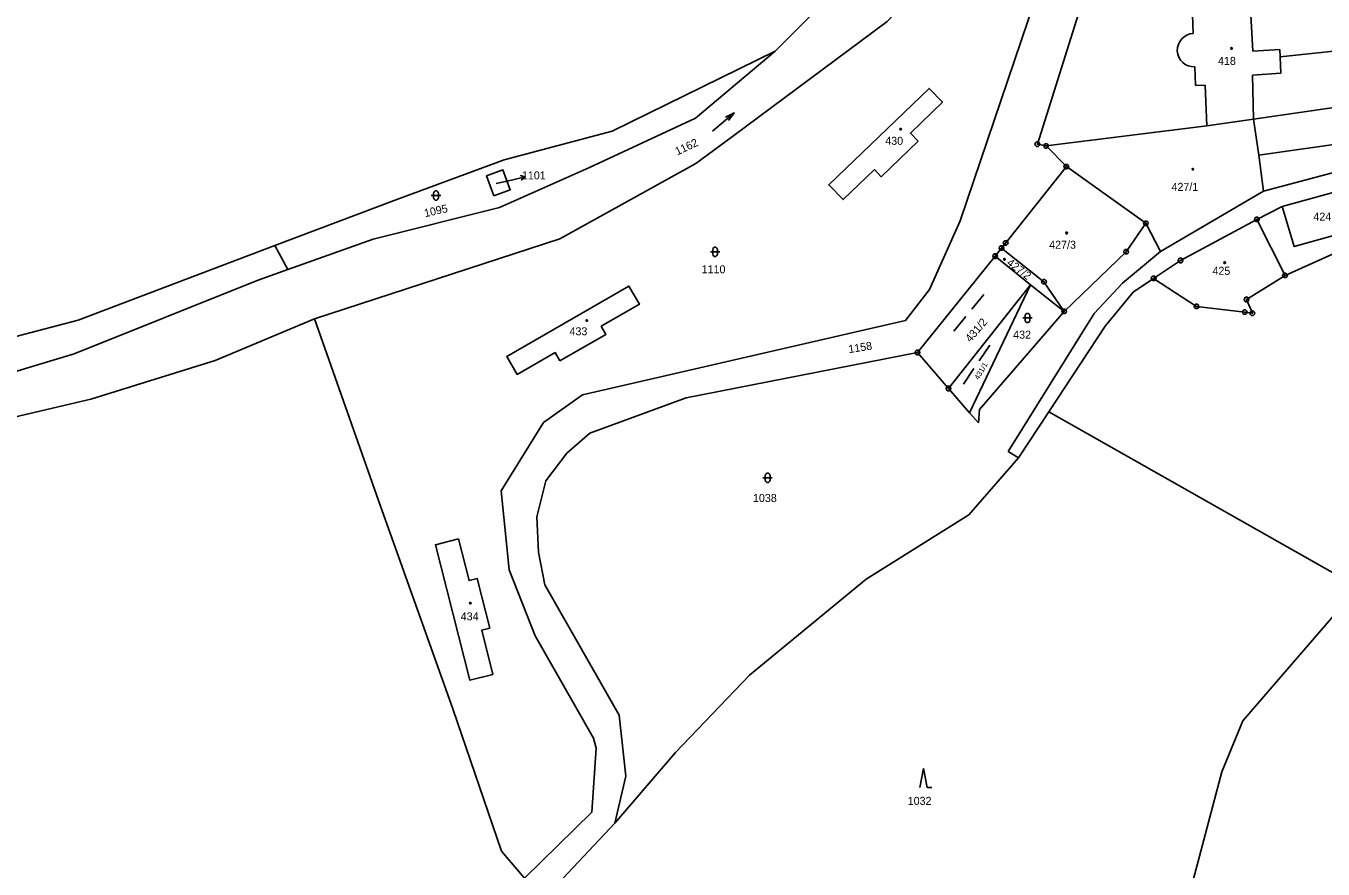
# Model space of a CAD drawing. Extents: x -812394 to -807601, y -1013098 to -1009266.
# Drawn here: x -811273.1 to -810997.6, y -1011891.6 to -1011712.3 of the extents above; entities that cross this region are included whole.
import ezdxf

# ---------------------------------------------------------------- set-up
doc = ezdxf.new("R2010")
doc.units = 0
for name, color, linetype in [('KN_HRANICE', 7, 'Continuous'), ('KN_KULTURY', 7, 'Continuous'), ('KN_MEZNIKY', 7, 'Continuous'), ('KN_PARCELY', 7, 'Continuous'), ('KN_SLUCKY', 7, 'Continuous')]:
    doc.layers.add(name, color=color, linetype=linetype)

# ---------------------------------------------------------------- blocks, each defined once
blk = doc.blocks.new('308')
blk.add_lwpolyline([(-0.75, 0), (0, 4), (0.75, 0), (1.75, 0)])
blk = doc.blocks.new('316')
for points in [[(-1, 1), (0.27, 1), (1, 1)], [(-0.5, 1.5), (-0.4, 1.79), (-0.15, 1.97), (0.16, 1.97), (0.41, 1.79), (0.51, 1.5), (0.51, 0.5), (0.41, 0.21), (0.16, 0.03), (-0.15, 0.03), (-0.4, 0.21), (-0.5, 0.5), (-0.5, 1.5)]]:
    blk.add_lwpolyline(points)
blk = doc.blocks.new('NAHRADNI_SYMBOL')
blk.add_lwpolyline([(0.09, 0.15), (0.18, 0), (0.09, -0.15), (-0.09, -0.15), (-0.18, 0), (-0.09, 0.15), (0.09, 0.15)])
blk = doc.blocks.new('802')
blk.add_line((-3, 0), (3, 0))
blk.add_lwpolyline([(1, 0.5), (3, 0), (1, -0.5)])
blk = doc.blocks.new('803')
for p, q in [((-7.5, 0), (-1.5, 0)), ((1.5, 0), (7.5, 0))]:
    blk.add_line(p, q)
blk = doc.blocks.new('10292')
blk.add_line((0, 3), (0, 0))
blk.add_lwpolyline([(-0.5, 2), (0, 3), (0.5, 2)])
blk = doc.blocks.new('105')
blk.add_line((-0.12, 0), (0.12, 0))
blk.add_lwpolyline([(0.15, 0.48), (0.4, 0.3), (0.5, 0.01), (0.4, -0.28), (0.15, -0.46), (-0.16, -0.46), (-0.41, -0.28), (-0.51, 0.01), (-0.41, 0.3), (-0.16, 0.48), (0.15, 0.48)])
blk = doc.blocks.new('402')
blk.add_lwpolyline([(0.09, 0.15), (0.18, 0), (0.09, -0.15), (-0.09, -0.15), (-0.18, 0), (-0.09, 0.15), (0.09, 0.15)])

msp = doc.modelspace()

# ---------------------------------------------------------------- linework, layer by layer
at = {"layer": 'KN_HRANICE'}
for p, q in [((-811036.27, -1011667.85), (-811058.25, -1011737.49)), ((-811113.97, -1011717.72), (-811101.04, -1011704.72)), ((-811025.3, -1011710.01), (-811025.13, -1011713.95)), ((-811148.58, -1011734.71), (-811113.97, -1011717.72)), ((-811024.65, -1011724.99), (-811024.82, -1011721.05)), ((-811022.63, -1011724.91), (-811024.65, -1011724.99)), ((-811022.25, -1011733.58), (-811022.63, -1011724.91)), ((-811022.25, -1011733.58), (-811012.33, -1011732.15)), ((-811012.33, -1011732.15), (-811011.17, -1011739.82)), ((-811171.54, -1011740.78), (-811148.58, -1011734.71)), ((-811056.39, -1011737.86), (-811022.25, -1011733.58)), ((-811058.25, -1011737.49), (-811056.39, -1011737.86)), ((-811056.39, -1011737.86), (-811052.09, -1011742.26)), ((-811011.17, -1011739.82), (-811010.19, -1011747.48)), ((-811010.19, -1011747.48), (-810977.33, -1011738.74)), ((-811194.29, -1011749.24), (-811171.54, -1011740.78)), ((-811052.09, -1011742.26), (-811064.98, -1011758.48)), ((-811035.21, -1011754.31), (-811052.09, -1011742.26)), ((-811012.74, -1011748.94), (-811010.19, -1011747.48)), ((-810990.56, -1011746.41), (-811006.21, -1011750.72)), ((-811220.22, -1011759.06), (-811194.29, -1011749.24)), ((-811199.35, -1011757.68), (-811172.54, -1011750.96)), ((-811032.06, -1011760.31), (-811012.74, -1011748.94)), ((-811006.21, -1011750.72), (-811011.62, -1011753.48)), ((-811074.63, -1011753.78), (-811081.18, -1011768.41)), ((-811039.37, -1011760.37), (-811035.21, -1011754.31)), ((-811035.21, -1011754.31), (-811032.06, -1011760.31)), ((-811011.62, -1011753.48), (-811005.63, -1011765.4)), ((-811262.02, -1011774.9), (-811220.22, -1011759.06)), ((-811217.49, -1011764.12), (-811220.22, -1011759.06)), ((-811217.49, -1011764.12), (-811199.35, -1011757.68)), ((-811065.85, -1011759.58), (-811067.22, -1011761.3)), ((-811064.98, -1011758.48), (-811065.85, -1011759.58)), ((-811056.84, -1011766.74), (-811065.85, -1011759.58)), ((-811005.63, -1011765.4), (-810987.54, -1011757.25)), ((-811067.22, -1011761.3), (-811083.69, -1011781.79)), ((-811067.22, -1011761.3), (-811059.74, -1011767.4)), ((-811052.53, -1011773.05), (-811039.37, -1011760.37)), ((-811032.06, -1011760.31), (-811040.13, -1011767.06)), ((-811224.02, -1011766.44), (-811217.49, -1011764.12)), ((-811262.9, -1011782.04), (-811224.02, -1011766.44)), ((-811077.11, -1011789.44), (-811059.74, -1011767.4)), ((-811059.74, -1011767.4), (-811072.69, -1011794.59)), ((-811059.74, -1011767.4), (-811052.53, -1011773.05)), ((-811052.53, -1011773.05), (-811056.84, -1011766.74)), ((-811040.13, -1011767.06), (-811046.19, -1011773.46)), ((-811037.93, -1011768.93), (-811033.54, -1011766.01)), ((-811081.18, -1011768.41), (-811086.29, -1011774.95)), ((-811043.81, -1011776.2), (-811037.93, -1011768.93)), ((-811070.51, -1011793.88), (-811052.53, -1011773.05)), ((-811046.19, -1011773.46), (-811064.47, -1011802.81)), ((-811014.19, -1011773.19), (-811012.57, -1011773.41)), ((-811296.53, -1011783.87), (-811262.02, -1011774.9)), ((-811154.9, -1011790.75), (-811088.72, -1011775.51)), ((-811086.29, -1011774.95), (-811088.72, -1011775.51)), ((-811055.79, -1011794.38), (-811043.81, -1011776.2)), ((-811132.85, -1011791.42), (-811083.69, -1011781.79)), ((-811083.69, -1011781.79), (-811077.11, -1011789.44)), ((-811291.86, -1011790.78), (-811262.9, -1011782.04)), ((-811077.11, -1011789.44), (-811072.69, -1011794.59)), ((-811153.33, -1011798.9), (-811132.85, -1011791.42)), ((-811072.69, -1011794.59), (-811070.75, -1011796.69)), ((-811070.75, -1011796.69), (-811070.51, -1011793.88)), ((-811055.79, -1011794.38), (-811062.22, -1011804.13)), ((-810990.1, -1011831.63), (-811055.79, -1011794.38)), ((-811158.17, -1011803.18), (-811153.33, -1011798.9)), ((-811162.67, -1011809.02), (-811158.17, -1011803.18)), ((-811064.47, -1011802.81), (-811062.22, -1011804.13)), ((-811062.22, -1011804.13), (-811072.81, -1011816.28)), ((-811164.61, -1011816.73), (-811162.67, -1011809.02)), ((-811164.22, -1011824.22), (-811164.61, -1011816.73)), ((-811072.81, -1011816.28), (-811094.61, -1011829.98)), ((-811162.9, -1011831.15), (-811164.22, -1011824.22)), ((-811147.06, -1011858.89), (-811162.9, -1011831.15)), ((-811094.61, -1011829.98), (-811119.39, -1011850.37)), ((-811014.6, -1011860.1), (-810990.1, -1011831.63)), ((-811152.56, -1011863.74), (-811164.95, -1011842)), ((-811119.39, -1011850.37), (-811135.1, -1011866.8)), ((-811145.65, -1011871.81), (-811147.06, -1011858.89)), ((-811019.07, -1011870.93), (-811014.6, -1011860.1)), ((-811152.56, -1011863.74), (-811151.94, -1011865.87)), ((-811151.94, -1011865.87), (-811152.86, -1011879.52)), ((-811135.1, -1011866.8), (-811148, -1011881.85)), ((-811148, -1011881.85), (-811145.65, -1011871.81)), ((-811025.42, -1011895.01), (-811019.07, -1011870.93)), ((-811152.86, -1011879.52), (-811167.19, -1011893.49)), ((-811162.39, -1011897.16), (-811148, -1011881.85)), ((-811167.19, -1011893.49), (-811172.1, -1011887.81))]:
    msp.add_line(p, q, dxfattribs=at)
for points in [[(-811123.04, -1011735.83), (-811090.17, -1011711.42), (-811052.04, -1011671.11)], [(-811074.63, -1011753.78), (-811047.22, -1011672.77), (-811052.04, -1011671.11)], [(-811172.54, -1011750.96), (-811153.38, -1011742.41), (-811130.88, -1011731.98), (-811113.97, -1011717.72)], [(-811211.84, -1011774.62), (-811159.7, -1011757.62), (-811130.79, -1011741.59), (-811123.04, -1011735.83)], [(-811011.62, -1011753.48), (-811027.82, -1011762.22), (-811033.54, -1011766.01)], [(-811033.54, -1011766.01), (-811024.43, -1011771.98), (-811014.19, -1011773.19)], [(-811012.57, -1011773.41), (-811013.82, -1011770.52), (-811005.63, -1011765.4)], [(-811440.11, -1011849.96), (-811421.34, -1011843.71), (-811392.71, -1011835.04), (-811348.09, -1011817.52), (-811325.66, -1011813.58), (-811310.88, -1011808.15), (-811285.31, -1011797.78), (-811259.35, -1011791.72), (-811232.94, -1011783.44), (-811211.84, -1011774.62)], [(-811211.84, -1011774.62), (-811198.18, -1011813.24), (-811182.45, -1011857.53), (-811172.1, -1011887.81)], [(-811164.95, -1011842), (-811170.42, -1011827.98), (-811172.16, -1011811.18), (-811163.19, -1011796.67), (-811154.9, -1011790.75)]]:
    msp.add_lwpolyline(points, dxfattribs=at)
for points in [[(-811083.54, -1011736.84), (-811085.2, -1011735.12), (-811078.41, -1011728.58), (-811081.26, -1011725.62), (-811102.55, -1011746.13), (-811099.51, -1011749.28), (-811092.87, -1011742.88), (-811091.4, -1011744.41)], [(-811173.73, -1011748.46), (-811175.25, -1011744.2), (-811171.79, -1011742.97), (-811170.25, -1011747.2)], [(-811159.68, -1011783.56), (-811149.9, -1011777.92), (-811150.9, -1011776.18), (-811142.78, -1011771.5), (-811145, -1011767.65), (-811170.97, -1011782.61), (-811168.77, -1011786.43), (-811160.71, -1011781.78)], [(-811174.55, -1011840.37), (-811177.23, -1011829.82), (-811178.98, -1011830.26), (-811181.24, -1011821.4), (-811186.11, -1011822.64), (-811178.79, -1011851.46), (-811173.9, -1011850.21), (-811176.29, -1011840.82)]]:
    msp.add_lwpolyline(points, close=True, dxfattribs=at)
msp.add_arc((-811024.97, -1011717.5), 3.55, 92.5841, 272.416, dxfattribs=at)
at = {"layer": 'KN_PARCELY'}
msp.add_line((-811173.23, -1011745.87), (-811169.97, -1011745.11), dxfattribs=at)
at = {"layer": 'KN_SLUCKY'}
for p, q in [((-811013.26, -1011702.91), (-811012.49, -1011717.69)), ((-810956.56, -1011713.43), (-811006.65, -1011718.94)), ((-811012.49, -1011717.69), (-811006.72, -1011717.38)), ((-811006.72, -1011717.38), (-811006.65, -1011718.94)), ((-811006.65, -1011718.94), (-811006.5, -1011722.41)), ((-811006.5, -1011722.41), (-811012.56, -1011722.82)), ((-811012.56, -1011722.82), (-811012.33, -1011732.15)), ((-811012.33, -1011732.15), (-810979.82, -1011727.46)), ((-810978.44, -1011735.16), (-811011.17, -1011739.82))]:
    msp.add_line(p, q, dxfattribs=at)
msp.add_lwpolyline([(-811006.21, -1011750.72), (-811003.67, -1011759.26), (-810988.18, -1011754.95)], dxfattribs=at)

# ---------------------------------------------------------------- block references
at = {"layer": 'KN_KULTURY'}
for name, p in [('402', (-811017, -1011717.11)), ('NAHRADNI_SYMBOL', (-811087.3, -1011734.32)), ('NAHRADNI_SYMBOL', (-811025.21, -1011742.82)), ('316', (-811186, -1011749.4)), ('NAHRADNI_SYMBOL', (-811052.04, -1011756.37)), ('316', (-811126.72, -1011761.38)), ('NAHRADNI_SYMBOL', (-811065.24, -1011761.97)), ('NAHRADNI_SYMBOL', (-811018.46, -1011762.68)), ('316', (-811060.35, -1011775.43)), ('NAHRADNI_SYMBOL', (-811153.97, -1011774.97)), ('316', (-811115.55, -1011809.42)), ('NAHRADNI_SYMBOL', (-811178.7, -1011835.04)), ('308', (-811082.43, -1011874.22))]:
    msp.add_blockref(name, p, dxfattribs=at)
at = {"layer": 'KN_KULTURY', "rotation": 40.221637}
msp.add_blockref('802', (-811124.97, -1011732.75), dxfattribs=at)
at = {"layer": 'KN_KULTURY', "xscale": 0.67}
for p, yscale, rotation in [((-811072.82, -1011773.33), 0.6699999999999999, 50.706765), ((-811071.16, -1011784.36), 0.67, 56.092568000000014)]:
    msp.add_blockref('803', p, dxfattribs=dict(at, yscale=yscale, rotation=rotation))
at = {"layer": 'KN_MEZNIKY'}
for p in [(-811058.25, -1011737.49), (-811056.39, -1011737.86), (-811052.09, -1011742.26), (-811035.21, -1011754.31), (-811011.62, -1011753.48), (-811065.85, -1011759.58), (-811064.98, -1011758.48), (-811067.22, -1011761.3), (-811039.37, -1011760.37), (-811027.82, -1011762.22), (-811005.63, -1011765.4), (-811056.84, -1011766.74), (-811033.54, -1011766.01), (-811013.82, -1011770.52), (-811052.53, -1011773.05), (-811024.43, -1011771.98), (-811014.19, -1011773.19), (-811012.57, -1011773.41), (-811083.69, -1011781.79), (-811077.11, -1011789.44)]:
    msp.add_blockref('105', p, dxfattribs=at)
at = {"layer": 'KN_PARCELY', "rotation": -76.95884900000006}
msp.add_blockref('10292', (-811169.97, -1011745.11), dxfattribs=at)

# ---------------------------------------------------------------- texts
at = {"layer": 'KN_PARCELY'}
for s, height, p in [('418', 1.7, (-811019.87, -1011720.63)), ('430', 1.7, (-811090.56, -1011737.62)), ('1101', 1.7, (-811167.75, -1011744.97)), ('1101', 0.1, (-811172.93, -1011745.76)), ('427/1', 1.7, (-811029.75, -1011747.41)), ('424', 1.7, (-810999.61, -1011753.73)), ('427/3', 1.7, (-811055.74, -1011759.71)), ('1110', 1.7, (-811129.57, -1011764.93)), ('425', 1.7, (-811021.05, -1011765.25)), ('433', 1.7, (-811157.64, -1011778.11)), ('432', 1.7, (-811063.39, -1011778.83)), ('1038', 1.7, (-811118.66, -1011813.54)), ('434', 1.7, (-811180.75, -1011838.71)), ('1032', 1.7, (-811085.79, -1011877.93))]:
    msp.add_text(s, height=height, dxfattribs=at).set_placement(p)
for s, height, rotation, p in [('1162', 1.7, 25.21, (-811134.72, -1011739.89)), ('1095', 1.7, 12.834, (-811188.31, -1011753.02)), ('427/2', 1.7, 323.148, (-811064.91, -1011763.01)), ('431/2', 1.7, 49.389, (-811072.45, -1011779.7)), ('1158', 1.7, 8.881, (-811098.25, -1011781.91)), ('431/1', 1.14, 60.103, (-811070.72, -1011787.68))]:
    msp.add_text(s, height=height, rotation=rotation, dxfattribs=at).set_placement(p)

doc.saveas('drawing.dxf')
